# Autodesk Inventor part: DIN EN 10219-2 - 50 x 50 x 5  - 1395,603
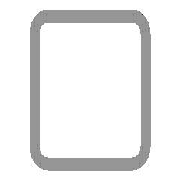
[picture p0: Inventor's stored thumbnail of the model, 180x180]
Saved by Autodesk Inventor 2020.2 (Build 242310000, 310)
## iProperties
IsCustomPart: 1
_CCFamilyMember: 16
_CCFamilyDisplayName: DIN EN 10219-2 (Quadratisches Hohlprofil - Kaltgeformt) - Kaltgeformte, geschweißte Baustahl-Hohlprofile aus unlegiertem Feinkorn-Baustahl
_FrameMemberDoc: Frame Member File
_Version: 15.0.0
_GetPNFromCC: 1
Created: 2019-01
Part Number: DIN EN 10219-2 - 50 x 50 x 5  - 1395,603
Material: Stahl, weich
Description: Kaltgeformte, geschweißte Baustahl-Hohlprofile aus unlegiertem Feinkorn-Baustahl
Document SubType Name: Modeling
Standard: DIN
Designer: lutzd
Standard Revision: 2006-07
Standards Organization: DIN
Language: de-DE
Size Designation: 50 x 50 x 5
Categories: <MemberInstance><Categories><Category DisplayName="Profile" InternalName="089c4875-fa83-4c05-b084-43b9cc11f5ed" Mnemonic="GRDR"><CategoryParameter DisplayName="
Stock Number: 50 x 50 x 5
Mass: 8870.57 g
Surface Area: 4545.11 cm^2
Volume: 1130.01 cm^3
Density: 7.85 g/cm^3
Appearance: Semi-Polished(8)
G_W: 50,000 mm
G_H: 50,000 mm
Mass: 8,871 kg
VLT_Material: Stahl, weich
+E59EB3B1-5893-404B-BCF4-A6CBA66C4CB4+SCHNITTDETAIL1: Schnittwinkel 30,00 grd
G_L: 1395,603 mm
Dimensions: 50x50x1395,6 mm
+4A345EEE-B90E-4910-9BC9-AC543564EEEF+SCHNITTDETAIL2: Schnittwinkel 90,00 grd
Author: lutzd
Revision Number: -
Title: Kaltgeformte, geschweißte Baustahl-Hohlprofile aus unlegiertem Feinkorn-Baustahl
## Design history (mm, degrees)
node "Startebene"
node "Endebene"
sketch "Skizze"
  geometry: L1 (-25, -15)-(-25, 15); L2 (-15, 25)-(15, 25); L3 (25, 15)-(25, -15); L4 (15, -25)-(-15, -25); L5 (-15, 20)-(15, 20); L6 (20, 15)-(20, -15); L7 (15, -20)-(-15, -20); L8 (-20, -15)-(-20, 15); L9 (0, 37.899)-(0, -37.899) reference; L10 (-37.899, 0)-(37.899, 0) reference; A1 r 10 centre (-15, -15) between (-25, -15) and (-15, -25); A2 r 10 centre (-15, 15) between (-15, 25) and (-25, 15); A3 r 10 centre (15, 15) between (25, 15) and (15, 25); A4 r 10 centre (15, -15) between (15, -25) and (25, -15); A5 r 5 centre (-15, 15) between (-15, 20) and (-20, 15); A6 r 5 centre (15, 15) between (20, 15) and (15, 20); A7 r 5 centre (15, -15) between (15, -20) and (20, -15); A8 r 5 centre (-15, -15) between (-20, -15) and (-15, -20)
  constraints: 16 end point, 16 point on circle, 8 centre point, 8 tangent, 4 parallel, 3 equal radius, 2 perpendicular, 7 other
  dimensions: "d7" = 10 radius of A1 (= G_IR); "d10" = 50 distance between parallel lines of L2 L4 (= G_H); "d11" = 50 distance between parallel lines of L1 L3 (= G_W); "d12" = 5 distance between parallel lines of L3 L6 (= G_T); "d15" = 25 distance between parallel lines of L2 L10 (= 0.5 x d10); "d16" = 25 distance between parallel lines of L9 L3 (= 0.5 x d11)
extrude "Körper" new body sketch "Skizze" stored distance "d3" = 1395.60254 (= G_L); taper "d4" = 0 deg
node "Driven Length"
  sketch "Sketch3"
    geometry: L1 (0, 0)-(10, 0) reference
    constraints: 2 end point, 1 horizontal
  workplane "Work Plane3"
  sketch "Sketch4"
    geometry: L1 (-2, 35)-(12, 35) reference; L2 (-2, 1430.603)-(12, 1430.603) reference
    dimensions: "d18" = 1395.60254 distance between parallel lines of L1 L2 (derived)
workplane "Arbeitsebene4"
feature "Trennen1"
workplane "Arbeitsebene5"
feature "Trennen2"
body "Solid1"
other parameters: "G_W" = 50 [user parameter; used in 1 equation term], "G_H" = 50 [user parameter; used in 1 equation term], "G_T" = 5 [user parameter; used in 1 equation term], "G_IR" = 10 [user parameter; used in 1 equation term], "G_L" = 1395.60254 (= d18) [user parameter; used in 1 equation term], "G_OFFSET_START" = -35 [user parameter; used in 1 equation term], "G_OFFSET_END" = 200.60254 [user parameter; used in 1 equation term], "d13" = 35 (= -G_OFFSET_START), "d14" = 1430.60254 (= G_OFFSET_END + B_L), "d17" = 90 deg
